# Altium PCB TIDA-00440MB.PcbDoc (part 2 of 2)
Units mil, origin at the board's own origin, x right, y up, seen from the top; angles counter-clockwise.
Board outline 4900 x 4330.71 mil, 4 copper layers (Top Layer, MidLayer1 (GND), MidLayer2 (PWR), Bottom Layer), stack 90 mil thick; 170 components, 89 nets, 419 pads, 132 vias.
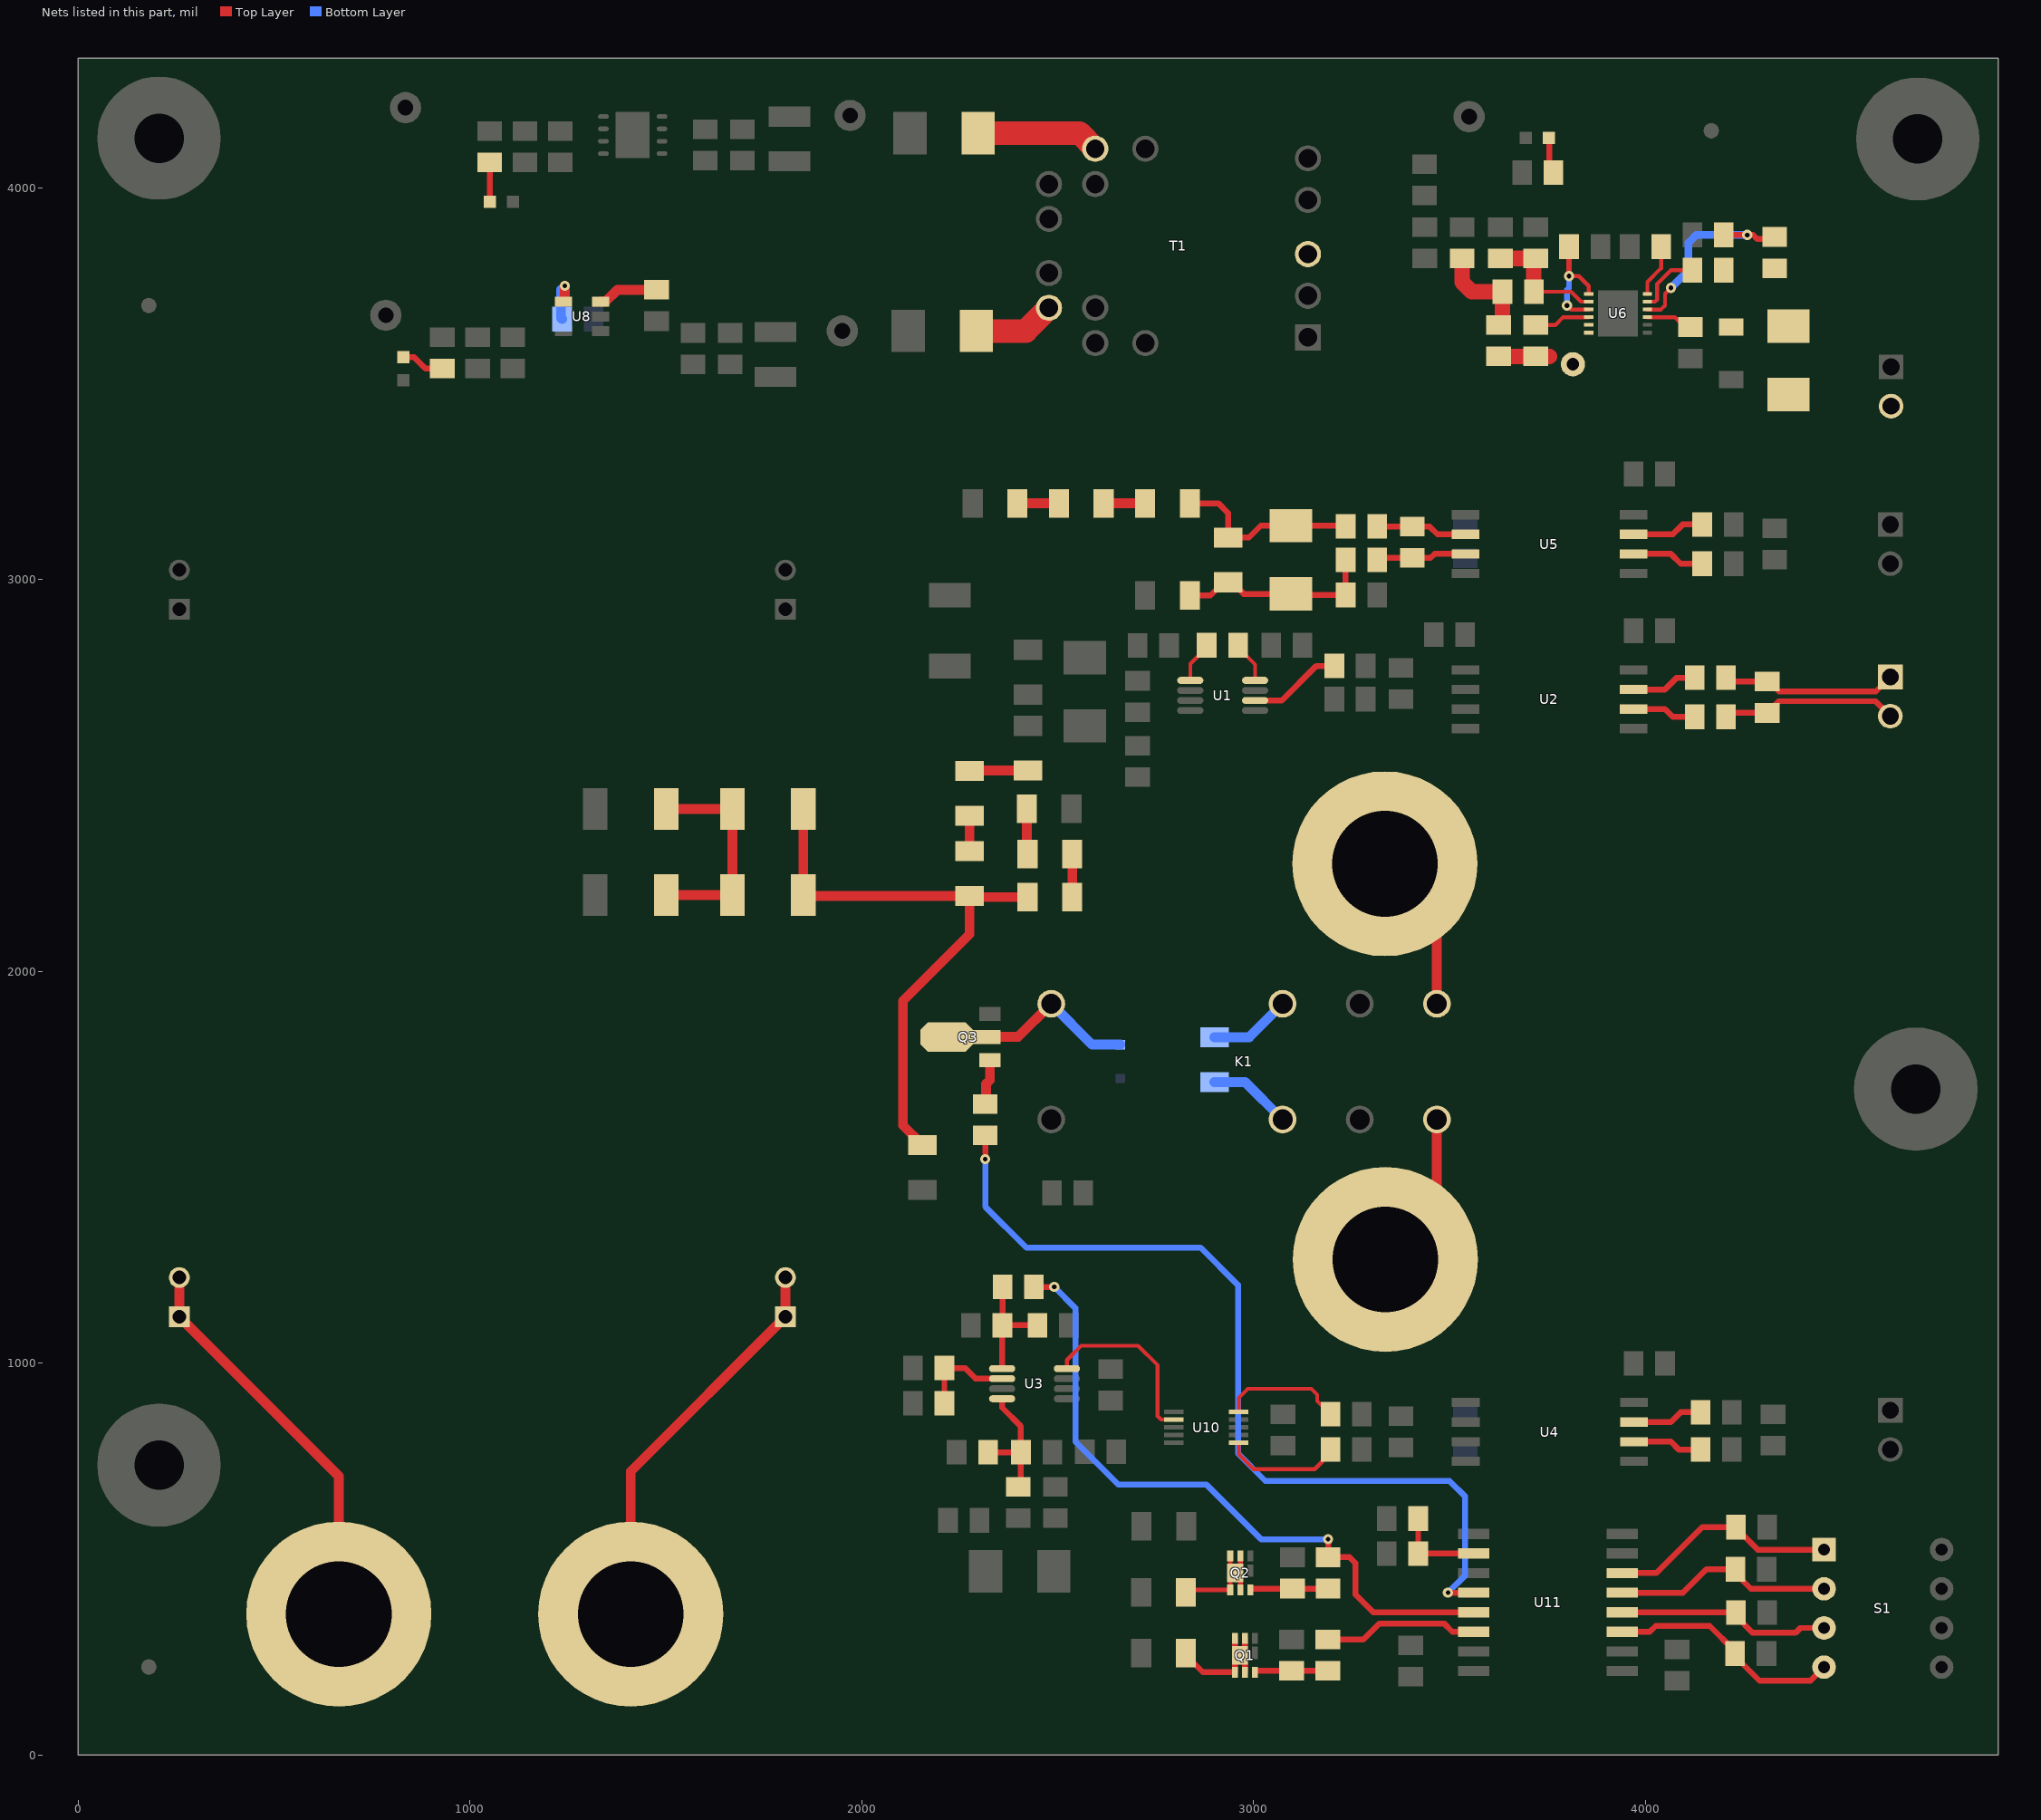
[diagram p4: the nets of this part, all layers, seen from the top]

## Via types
v1: diameter 26, hole 12, Top Layer to Bottom Layer, 122 vias
v2: diameter 19.68, hole 7.87, Top Layer to Bottom Layer, 10 vias

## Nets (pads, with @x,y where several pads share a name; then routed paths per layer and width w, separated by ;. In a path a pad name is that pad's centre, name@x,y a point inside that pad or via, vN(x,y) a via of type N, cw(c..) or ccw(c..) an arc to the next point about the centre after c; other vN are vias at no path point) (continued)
NetC6_2: C6.2 C43.1 R24.2 U3.8 | length 331.4
  Top Layer w15: C43.1@2322,773 C6.2@2406,773 ; U3.8@2358.01,909.61 2358.01,886.99 2406,839 C6.2@2406,773 ; R24.2@2399,685 2406,692 C6.2@2406,773
NetC7_1: C7.1 R22.2 U5.2 | length 233.7
  Top Layer w15: R22.2@3315,3136 C7.1@3405,3136 3449,3136 3469,3116 U5.2@3540.43,3116
NetC7_2: C7.2 R29.2 U5.3 | length 231.6
  Top Layer w15: R29.2@3315,3051 3320,3056 C7.2@3405,3056 3452,3056 3462,3066 U5.3@3540.43,3066
NetC11_1: C11.1 U6.6 | length 135.4
  Top Layer w10: U6.6@4004.8,3729.21 4004.8,3759.8 4040,3795 C11.1@4040,3850
NetC22_1: C22.1 U6.10 | length 143.5
  Top Layer w10: C22.1@3720,3650 3770,3650 3790.16,3670.16 U6.10@3855.2,3670.16
NetC22_2: C22.2 R48.1 SW.1 T1.3 U6.11 U6.12 | length 110
  Top Layer w40: R48.1@3645,3570 3755,3570
NetC24_2: C24.2 C31.2 R48.2 | length 262.5
  Top Layer w40: C24.2@3532,3820 3532,3760 3557,3735 C31.2@3635,3735 3635,3660 R48.2@3625,3650
NetC28_1: C28.1 C29.1 D4.1 R46.2 R49.1 U6.3 | length 120.6
  Top Layer w10: U6.3@4004.8,3670.16 4074.84,3670.16 4100,3645 C29.1@4115,3645
NetC30_1: C30.1 U8.4 | length 118.3
  Top Layer w25: U8.4@1238.44,3709.4 1242,3712.96 v1(1242,3750)
  Bottom Layer w25: 1232,3740 1232,3668 C30.1@1235,3665
NetC31_1: C31.1 R50.1 R52.2 U6.8 | length 305.7
  Top Layer w10: C31.1@3725,3735 3810,3735 3835.47,3709.53 U6.8@3855.2,3709.53
  Top Layer w40: R50.1@3630,3820 R52.2@3720,3820 ; C31.1@3715,3735 R52.2@3715,3810
NetC34_1: C34.1 U6.7 U6.9 | length 292.7
  Top Layer w10: v1(3800,3700) 3810.16,3689.84 U6.9@3855.2,3689.84 ; v1(3805,3775) 3830,3775 3855.2,3749.8 U6.7@3855.2,3729.21
  Top Layer w15: v1(3805,3775) C34.1@3805,3850
  Bottom Layer w15: v1(3800,3700) 3800,3740 3805,3745 v1(3805,3775)
NetD1_2: D1.2 K1.8 Q3.2 Q3.4 | length 521.7
  Top Layer w25: Q3.4@2216.57,1833 Q3.2@2318.93,1833 2398.76,1833 K1.8@2483.4,1917.64
  Bottom Layer w25: K1.8@2483.4,1917.64 2587.73,1813.31 D1.2@2660,1813.31
NetD2_2: D2.2 T1.11 | length 327.2
  Top Layer w60: D2.2@2297.01,4140 2555.63,4140 T1.11@2595.6,4100.03 ; D2.2@2299.5,4125.5 D2.2@2299.5,4137.51
NetD3_2: D3.2 T1.15 | length 210
  Top Layer w60: D3.2@2292.01,3635 2418.36,3635 T1.15@2477.49,3694.13
NetD4_2: D4.2 J5.2
NetD5_1: D5.1 R19.1 R22.1 R27.2 | length 483.9
  Top Layer w15: R19.1@2837.09,3195 2910,3195 2935,3170 R27.2@2935,3107.77 2988.27,3107.77 3018.51,3138.01 D5.1@3095,3138.01 3232.99,3138.01 R22.1@3235,3136
NetD5_2: D5.2 R27.1 R29.1 R56.2 R57.2 | length 515.3
  Top Layer w15: R57.2@2837.09,2960 2890,2960 2923.6,2993.6 R27.1@2935,2993.6 2945.24,2993.6 2974.84,2963.99 D5.2@3095,2963.99 3107.99,2963.99 3110.98,2961 R56.2@3235,2961 R29.1@3235,3051
NetD6_1: D6.1 R1.2 | length 93.3
  Top Layer w15: D6.1@3754.53,4128 3754.53,4049.47 R1.2@3765,4039
NetD7_1: D7.1 R53.2 | length 100.2
  Top Layer w15: R53.2@1050,4065 1050,3965.47 D7.1@1050.47,3965
NetD8_1: D8.1 R54.2 | length 111.5
  Top Layer w15: D8.1@829.69,3568.46 856.54,3568.46 886,3539 R54.2@929,3539
NetJ1_1: J1.1 JD1.1 JD1.2 | length 1027.7
  Top Layer w25: JD1.2@257.76,1219 JD1.1@257.76,1119 665,711.76 J1.1@665,360
NetJ2_1: J2.1 JD2.1 JD2.2 | length 1022.6
  Top Layer w25: J2.1@1410,360 1410,724 JD2.1@1805,1119 JD2.2@1805,1219
NetJ3_1: J3.1 K1.4 | length 446.9
  Top Layer w25: J3.1@3336,1230 3467.65,1361.65 K1.4@3467.65,1622.36
NetJ4_1: J4.1 K1.5 | length 412.3
  Top Layer w25: J4.1@3335,2275 3467.65,2142.35 K1.5@3467.65,1917.64
NetK1_2: K1.2 R35.2 | length 213.5
  Bottom Layer w25: R35.2@2900,1717.91 2978.4,1717.91 K1.2@3073.95,1622.36
NetK1_7: K1.7 R35.1 | length 209.4
  Bottom Layer w25: R35.1@2900,1832.09 2988.4,1832.09 K1.7@3073.95,1917.64
NetQ1_1: Q1.1 Q1.2 Q1.5 Q1.6 Q1.7 R11.1 | length 268.2
  Top Layer w15: R11.1@2832.09,260 2832.09,249.76 2870.16,211.69 Q1.1@2952.21,211.69 Q1.7@2952.21,242.21 ; Q1.7@2952.21,267.79 Q1.6@2952.21,298.31 ; Q1.2@2977.8,211.69 Q1.7@2977.8,242.2 ; Q1.7@2977.8,267.8 Q1.5@2977.8,298.31
NetQ1_3: Q1.3 R14.2 R16.2 | length 187.1
  Top Layer w15: Q1.3@3003.39,211.69 3006.7,215 R16.2@3097.11,215 R14.2@3189.11,215
NetQ2_1: Q2.1 Q2.2 Q2.5 Q2.6 Q2.7 R12.1 | length 268.1
  Top Layer w12: R12.1@2832.09,418 2835.78,421.69 Q2.1@2940.41,421.69 Q2.7@2940.41,452.21 ; Q2.6@2940.41,508.31 2940.41,477.79 Q2.7@2953.2,465 2966,477.8 Q2.5@2966,508.31 ; Q2.2@2966,421.69 Q2.7@2966,452.2
NetQ2_3: Q2.3 R15.2 R17.2 | length 199.8
  Top Layer w15: Q2.3@2991.59,421.69 2994.9,425 R17.2@3099,425 R15.2@3190,425
NetQ3_1: Q3.1 R36.1 | length 116
  Top Layer w25: R36.1@2317,1662 2317,1713 2326.8,1722.8 Q3.1@2326.8,1773.94
NetR2_2: R2.2 R59.1 R61.2 R62.1 | length 557.8
  Top Layer w25: R61.2@1500.55,2195 R62.1@1669.45,2195 R59.1@1669.45,2415 R2.2@1500.55,2415
NetR3_2: R3.2 R58.1 | length 149.3
  Top Layer w25: R58.1@2275,2512.09 2275.83,2512.91 R3.2@2424,2512.91
NetR4_1: R4.1 U1.6 | length 238.8
  Top Layer w15: U1.6@3003.68,2691.89 3071.89,2691.89 3160,2780 R4.1@3206,2780
NetR5_1: R5.1 U2.7 | length 168.9
  Top Layer w15: U2.7@3969.57,2720 4050,2720 4080,2750 R5.1@4126,2750
NetR7_1: R7.1 U2.6 | length 164.7
  Top Layer w15: U2.6@3969.57,2670 4050,2670 4070,2650 R7.1@4126,2650
NetR10_1: R10.1 U1.1 | length 124.2
  Top Layer w10: U1.1@2838.32,2743.07 2838.32,2785.32 2880.69,2827.69 R10.1@2880.69,2849.69
NetR10_2: R10.2 U1.8 | length 124.4
  Top Layer w10: R10.2@2960.69,2849.69 2960.69,2826.31 3003.68,2783.32 U1.8@3003.68,2743.07
NetR18_1: R18.1 U10.10 | length 316
  Top Layer w10: U10.10@2962,876 2962,912 2985,935 3147.25,935 3162.25,920 3162.25,903.75 R18.1@3196,870
NetR19_2: R19.2 R65.1 | length 105.8
  Top Layer w25: R65.1@2617.09,3195 R19.2@2722.91,3195
NetR21_1: R21.1 U4.7 | length 180.8
  Top Layer w15: U4.7@3970.57,850 4065,850 4090,875 R21.1@4141,875
NetR23_1: R23.1 U4.6 | length 178.7
  Top Layer w15: U4.6@3970.57,800 4065,800 4085,780 R23.1@4141,780
NetR25_1: R25.1 U10.6 | length 305.5
  Top Layer w10: U10.6@2962,797.2 2962,768 3000,730 3156,730 3196,770 R25.1@3196,780
NetR26_1: R26.1 U5.7 | length 185.8
  Top Layer w15: U5.7@3969.57,3116 4070,3116 4095,3141 R26.1@4145,3141
NetR28_1: R28.1 U5.6 | length 185.8
  Top Layer w15: U5.6@3969.57,3066 4065,3066 4090,3041 R28.1@4145,3041
NetR30_2: R30.2 R33.2 U3.6 | length 248.6
  Top Layer w15: R30.2@2210.69,898 R33.2@2210.69,988 2263,988 2290.2,960.8 U3.6@2358.01,960.8
NetR31_2: R31.2 R32.2 R34.2 U3.5 | length 299
  Top Layer w15: U3.5@2358.01,986.39 2358.01,1096.32 R34.2@2358.69,1097 ; R32.2@2359,1195 2358.69,1194.69 R34.2@2358.69,1097 ; R31.2@2448.68,1097 R34.2@2358.69,1097
NetR37_1: R37.1 S1.1 U11.6 | length 589.1
  Top Layer w15: U11.6@3940.4,464.64 4027.64,464.64 4145,582 R37.1@4231,582 4231,580.07 4286.53,524.53 S1.1@4456,524.53
NetR38_1: R38.1 S1.2 U11.5 | length 566.5
  Top Layer w15: U11.5@3940.4,414.64 4096,414.64 4155.36,474 R38.1@4230,474 4230,464 4269.47,424.53 S1.2@4456,424.53
NetR39_1: R39.1 S1.3 U11.4 | length 527
  Top Layer w15: U11.4@3940.4,364.64 R39.1@4210.37,364.64 ; R39.1@4231,364 4231,355 4274,312 4383,312 4395.53,324.53 S1.3@4456,324.53
NetR40_1: R40.1 S1.4 U11.3 | length 609.6
  Top Layer w15: U11.3@3940.4,314.64 4011,314.64 4026.36,330 4164,330 4226,268 R40.1@4226,250 ; R40.1@4229,259 4229,252 4291,190 4421.47,190 S1.4@4456,224.54
NetR41_2: R41.2 R42.2 U11.10 | length 231.7
  Top Layer w15: R42.2@3420,604 R41.2@3420,514 3420.64,514.64 U11.10@3561.4,514.64
NetR43_2: R43.2 R63.1 | length 115.8
  Top Layer w25: R43.2@2420.91,2415 2420.91,2302 R63.1@2422.91,2300
NetR44_1: R44.1 R58.2 | length 90.8
  Top Layer w25: R44.1@2275,2307.09 R58.2@2275,2397.91
NetR44_2: R44.2 R45.2 R59.2 R60.2 R62.2 | length 1521.4
  Top Layer w25: R59.2@1850.55,2415 R62.2@1850.55,2195 1852.64,2192.91 R44.2@2275,2192.91 ; R45.2@2155,1557.09 2105,1607.09 2105,1925 2275,2095 R44.2@2275,2192.91 ; R60.2@2422.91,2190 2277.91,2190 R44.2@2275,2192.91
NetR46_1: R46.1 R51.2 U6.4 | length 528.8
  Top Layer w10: U6.4@4004.8,3689.84 4039.84,3689.84 4050,3700 4050,3730 v1(4065,3745)
  Top Layer w15: R51.2@4200,3880 v1(4260,3880) 4275,3880 4285,3870 4325,3870 R46.1@4330,3875
  Bottom Layer w20: v1(4065,3745) 4110,3790 4110,3860 4130,3880 v1(4260,3880)
NetR47_1: R47.1 U8.3 | length 155.7
  Top Layer w25: U8.3@1332.93,3709.4 1345.4,3709.4 1376,3740 R47.1@1476,3740
NetR49_2: R49.2 U6.5 | length 172
  Top Layer w10: U6.5@4004.8,3709.53 4024.53,3709.53 4030,3715 4030,3755 4065,3790 R49.2@4120,3790
NetR60_1: R60.1 R63.2 | length 110
  Top Layer w25: R60.1@2537.09,2190 R63.2@2537.09,2300
NetR64_1: R64.1 R65.2 | length 105.8
  Top Layer w25: R64.1@2397.09,3195 R65.2@2502.91,3195
NetU3_4: U3.4 U10.2 | length 464.1
  Top Layer w10: U3.4@2523.36,986.39 2523.36,1008.36 2560,1045 2705,1045 2755,995 2755,865 2763.7,856.3 U10.2@2796,856.3
RDM(+): C3.1 J7.1 R5.2 | length 454.7
  Top Layer w15: R5.2@4206,2750 4206,2740 C3.1@4311,2740 4316,2740 4341,2715 4588,2715 J7.1@4625,2752
RDM(-): C3.2 J7.2 R7.2 | length 457.2
  Top Layer w15: R7.2@4206,2650 4206,2660 C3.2@4311,2660 4341,2690 4587,2690 J7.2@4625,2652
RELAY: R36.2 U11.12 | length 2299.2
  Top Layer w15: v1(2315,1521) R36.2@2315,1582 ; v1@3492,415 v1@3496,415 ; v1@3492.36,414.64 v1@3493,414 ; v1@3496.18,414.82 3496.36,414.64 U11.12@3561.4,414.64
  Bottom Layer w15: v1(2315,1521) 2315,1400 2420,1295 2865,1295 2960,1200 2960,770 3030,700 3500,700 3540,660 3540,458.64 v1(3496,414.64)
SW1: R14.1 U11.14 | length 398.1
  Top Layer w15: R14.1@3189.11,295 3280,295 3321,336 3486,336 3507.36,314.64 U11.14@3561.4,314.64
SW2: R15.1 R32.1 U11.13 | length 1739.9
  Top Layer w15: R32.1@2439,1195 v1(2491,1195) ; v1(3190,551) R15.1@3190,505 3245,505 3260,490 3260,410 3305.36,364.64 U11.13@3561.4,364.64
  Bottom Layer w15: v1(2491,1195) 2545,1141 2545,800 2655,690 2880,690 3019,551 v1(3190,551)
pads on no net: FID1.1 FID2.1 FID3.1 FID4.1 FID5.1 FID6.1 H1.1 H2.1 H3.1 H4.1 LBL1.0 T1.1 T1.2 T1.5 T1.6 T1.7 T1.9 T1.10 T1.13 T1.14 U7.8 U11.7

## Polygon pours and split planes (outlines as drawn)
NetD4_2 on Top Layer "Multi-Layer-No Net" (solid, remove dead copper, pour order 28): 4286.5,3495 4301.5,3510 4495,3510 4530,3475 4655,3475 4680,3450 4680,3310 4655,3285 4320,3285 4285,3320 4286.5,3321.5
NetC22_2 on Top Layer "Multi-Layer-No Net" (solid, remove dead copper, pour order 23): 3105,3850 3120,3865 3285,3865 3350,3800 3350,3675 3430,3595 3805,3595 3815,3605 3815,3640 3830,3655 3865,3655 3865,3520 3845,3500 3365,3500 3250,3615 3250,3745 3200,3795 3110,3795 3105,3800
GND on Top Layer "Multi-Layer-No Net" (solid, remove dead copper, pour order 36): 3100,4250 3125,4275 4465,4275 4510,4230 4510,3985 4565,3930 4795,3930 4825,3900 4825,1950 4775,1900 4545,1900 4495,1850 4495,1545 4540,1500 4775,1500 4825,1450 4825,75 4800,50 3925,50 3900,75 3900,3275 3700,3475 3225,3475 3100,3600
5V_VCC2 on Top Layer "Multi-Layer-No Net" (solid, remove dead copper, pour order 20): 1250,3635 1180,3635 1165,3650 1165,3710 1130,3750 770,3750 715,3695 715,3605 735,3585 770,3585 800,3615 865,3615 885,3595 1245,3595 1250,3600
5V_VCC1 on Top Layer "Multi-Layer-No Net" (solid, remove dead copper, pour order 27): 1355,4115 1350,4110 1275,4110 1265,4120 1015,4120 1000,4135 1000,4150 985,4165 790,4165 770,4185 770,4255 785,4270 1340,4270 1355,4255
3V3 on Top Layer "Multi-Layer-No Net" (solid, remove dead copper, pour order 21): 3120,4000 3320,4000 3330,4000 3335,4005 3460,4005 3555,4005 3630,4005 3665,3970 3665,3890 3665,3880 3660,3875 3520,3875 3320,3875 3275,3920 3260,3935 3140,3935 3120,3935 3105,3950 3105,3990 3105,3995 3110,4000 3120,4000
ISENSE on Top Layer "Multi-Layer-No Net" (solid, remove dead copper, pour order 30): 2460,630 2560,630 2615,685 2720,685 2740,665 2740,165 2700,125 2470,125 2450,145 2450,535 2460,545
MID on Top Layer "Multi-Layer-No Net" (solid, remove dead copper, pour order 31): 2430,630 2275,630 2270,625 2270,535 2250,515 2210,515 2180,485 2180,235 2215,200 2320,200 2355,235 2355,490 2430,565
MID on Top Layer "Multi-Layer-No Net" (solid, remove dead copper, pour order 29): 2805,550 2815,540 2980,540 2985,535 2985,455 3030,455 3035,460 3035,475 3040,480 3135,480 3140,485 3140,590 3060,670 2820,670 2805,655
NetC28_1 on Top Layer "Multi-Layer-No Net" (solid, remove dead copper, pour order 26): 4060,3675 4060,3630 4070,3620 4275,3620 4295,3600 4470,3600 4490,3620 4490,3800 4470,3820 4175,3820 4175,3725 4160,3710 4095,3710
Net6V_VCC1_1 on Top Layer "Multi-Layer-No Net" (solid, remove dead copper, pour order 19): 1475,4120 1480,4115 1540,4115 1550,4125 1610,4125 1730,4125 1760,4155 1860,4155 1900,4155 2040,4015 2140,4015 2145,4015 2165,4035 2165,4235 2165,4240 2125,4280 1865,4280 1495,4280 1475,4260 1475,4120
Net6V_VCC2_1 on Top Layer "Multi-Layer-No Net" (solid, remove dead copper, pour order 22): 1425,3640 1445,3660 1445,3685 1525,3685 1550,3710 1550,3750 1580,3780 2120,3780 2160,3740 2160,3510 2125,3475 2010,3475 1880,3605 1505,3605 1475,3575 1475,3500 1450,3475 1330,3475 1310,3495 1310,3630 1320,3640
GND1 on MidLayer1 (GND) "Multi-Layer-No Net" (solid, remove dead copper, pour order 25): 2750,4255 2730,4275 425,4275 400,4250 400,3975 370,3945 85,3945 50,3910 50,975 100,925 380,925 425,880 425,775 475,725 1650,725 1750,625 1750,100 1800,50 3575,50 3600,75 3600,1615 3560,1655 2780,1655 2700,1735 2700,1970 2670,2000 685,2000 450,2235 450,3730 670,3950 1175,3950 1225,4000 2425,4000 2450,3975 2705,3975 2750,4020
GND on MidLayer1 (GND) "Multi-Layer-No Net" (solid, remove dead copper, pour order 35): 3100,4250 3125,4275 4475,4275 4500,4250 4500,3950 4525,3925 4800,3925 4825,3900 4825,1925 4800,1900 4590,1900 4500,1810 4500,1600 4600,1500 4805,1500 4825,1480 4825,75 4800,50 3925,50 3900,75 3900,3275 3700,3475 3225,3475 3100,3600
GND2 on MidLayer1 (GND) "Multi-Layer-No Net" (solid, remove dead copper, pour order 33): 2750,3725 2700,3775 795,3775 715,3695 715,3555 800,3470.33 800,2400 875,2325 3000,2325 3050,2275 3050,2125 3175,2000 3175,1900 3200,1875 3550,1875 3575,1900 3575,3175 3550,3200 2975,3200 2750,3425
5V_VCC1 on MidLayer2 (PWR) "Multi-Layer-No Net" (solid, remove dead copper, pour order 24): 2750,4255 2730,4275 425,4275 400,4250 400,3975 370,3945 85,3945 50,3910 50,975 100,925 380,925 425,880 425,775 475,725 1650,725 1750,625 1750,100 1800,50 3575,50 3600,75 3600,1615 3560,1655 2780,1655 2700,1735 2700,1970 2670,2000 685,2000 450,2235 450,3730 670,3950 1175,3950 1225,4000 2425,4000 2450,3975 2705,3975 2750,4020
3V3 on MidLayer2 (PWR) "Multi-Layer-No Net" (solid, remove dead copper, pour order 34): 3100,4250 3125,4275 4475,4275 4500,4250 4500,3950 4525,3925 4800,3925 4825,3900 4825,1925 4800,1900 4590,1900 4500,1810 4500,1600 4600,1500 4805,1500 4825,1480 4825,75 4800,50 3925,50 3900,75 3900,3275 3700,3475 3225,3475 3100,3600
5V_VCC2 on MidLayer2 (PWR) "Multi-Layer-No Net" (solid, remove dead copper, pour order 32): 2750,3725 2700,3775 795,3775 715,3695 715,3555 800,3470.33 800,2400 875,2325 3000,2325 3050,2275 3050,2125 3175,2000 3175,1900 3200,1875 3550,1875 3575,1900 3575,3175 3550,3200 2975,3200 2750,3425

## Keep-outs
Top Layer:
  lines w10: 2780,4330.71 2781,4329.71 2781,3513 3049,3245 3555,3245 3615,3185 3615,1425 3615,933.52 3615,-20 3880,-20 3885,-20 3885,45 3885,980 3885,3255 3690,3450 3214,3450 3086,3578 3086,4330.71 2801,4330.71 2780,4330.71
MidLayer1 (GND):
  lines w10: 2781,4329.71 2781,3513 3049,3245 3555,3245 3615,3185 3615,-20 3885,-20 3885,3255 3690,3450 3214,3450 3086,3578 3086,4330.71
MidLayer2 (PWR):
  lines w10: 2781,3513 3049,3245 3555,3245 3615,3185 3615,-20 3885,-20 3885,3255 3690,3450 3214,3450 3086,3578 3086,4330.71 3085,4329.71 2781,4329.71 2781,3513
Bottom Layer:
  lines w10: 3086,4330.71 3085,4329.71 ; 3085,4329.71 2781,4329.71 2781,3513 3049,3245 3555,3245 3615,3185 3615,-20 3885,-20 3885,3255 3690,3450 3214,3450 3085,3579 3085,4329.71
Keep-Out Layer:
  lines w8: 25,25 4875,25 4875,4305 25,4305 25,25
  text ".Layer_Name" at 132,-1113.49 h60

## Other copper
Top Layer:
  pour cut-out: 4077,3852 4162,3852 4163,3851 4163,3832.96 4077.54,3832.96 4077,3833.5
  text ".Layer_Name" at 132,-1113.49 h60
MidLayer1 (GND):
  text ".Layer_Name" at 120,-1110 h60
MidLayer2 (PWR):
  text ".Layer_Name" at 120,-1110 h60
Bottom Layer:
  text ".Layer_Name" at 132,-1113.49 h60

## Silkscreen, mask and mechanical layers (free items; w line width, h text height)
Top Overlay:
  circle w6: c2484.69,1498 r11.31
  lines w6: 1945,3715 1945,3775 ; 1970,4070 1970,4110 ; 2385.31,830 2391,830 2398,823 ; 2630,2900 2636,2894 2646,2894 2660,2880 ; 2655,547 2573,547 ; 2796,2621 2796,2626 2777,2645 2756,2645 ; 3554,3981 3578,3957 3595,3957 3610,3942 ; 3608,3981 3619,3970 3661,3970 3686,3945 ; 4800,425 4815,425 ; 2573,547 2574,547 2581,540 2581,555 2573,547 ; 2756,2645 2762,2639 2763,2639 2763,2652 2756,2645 ; 3610,3942 3610,3952 3600,3942 3610,3942 ; 3686,3945 3686,3955 3676,3945 3686,3945 ; 2835,785 2835,875 2840,880 2850,890 2925,890 2925,785 2835,785 ; 3650,175 3825,175 3850,200 3850,600 3650,600 3650,175 ; 4525,175 4525,550 4550,575 4695,575 4695,175 4525,175
  lines w10: 3207,3309 3207,3210 ; 3207,3210 3197,3220 3218,3220 3208,3210 3207,3210
  text "GND" at 4550,3660 h60
  text "VIN+" at 4530,3255 h60
  text "MATCH JD1 TO JD4 WHILE" at 610,1635 h60 r90
  text "MOUNTING DAUGHTER BOARD" at 750,1635 h60 r90
  text "JD1 AND JD2 - INPUT" at 925,1630 h60 r90
  text "JD3 AND JD4 - OUTPUT" at 1060,1625 h60 r90
  text "MUX" at 4800,530 h30
  text "RELAY" at 4855,355 h30 r90
  text "SW2" at 4800,305 h30
  text "SW1" at 4805,205 h30
  text "HV_DC(-)" at 1780,140 h50 r90
  text "HV_DC(+)" at 359,130 h50 r90
  text "TIDA-00440MB-E2" at 1945,120 h80
  text ".Layer_Name" at 132,-1113.49 h60
Bottom Overlay:
  text ".Layer_Name" at 132,-1113.49 h60
Top Paste:
  text ".Layer_Name" at 132,-1113.49 h60
Bottom Paste:
  text ".Layer_Name" at 132,-1113.49 h60
Top Solder:
  text ".Layer_Name" at 132,-1113.49 h60
Bottom Solder:
  text ".Layer_Name" at 132,-1113.49 h60
Drill Guide:
  text ".Layer_Name" at 132,-1113.49 h60
M1 Board Outline:
  the board outline again, w10
M2 Board Dimensions:
  rectangle: -445.5,-540.5 -320.5,-415.5
  rectangle: -320.5,-665.5 54.5,-540.5
  lines w7: -445.5,-540.5 554.5,-540.5 ; -320.5,-665.5 -320.5,-415.5 ; -195.5,-665.5 -195.5,-415.5 ; 54.5,-665.5 54.5,-415.5 ; 304.5,-665.5 304.5,-415.5 ; -445.5,-665.5 554.5,-665.5 554.5,-415.5 -445.5,-415.5 -445.5,-665.5
  lines w10: -445.5,-730.5 -445.5,-710.5 ; -385.5,-740.5 -445.5,-720.5 ; -385.5,-700.5 -445.5,-720.5 ; -221.42,-720.5 -445.5,-720.5 ; 330.42,-720.5 554.5,-720.5 ; 494.5,-740.5 554.5,-720.5 ; 494.5,-700.5 554.5,-720.5 ; 554.5,-730.5 554.5,-710.5
  text "1000 (mil)" at -211.42,-756.49 h60
M3 3D STEP Top:
  text ".Layer_Name" at 132,-1113.49 h60
M4 3D STEP Bottom:
  text ".Layer_Name" at 132,-1113.49 h60
M5 Assembly Top:
  circle w6: c1333,3600 r4.85
  circle w10: c3138.79,3620 r21.21
  circle w10: c2484.5,1620 r25.5
  lines w6: 1275.84,3610.98 1288.98,3610.98 1295.53,3617.53 1295.53,3733.02 1275.84,3733.02 1275.84,3610.98
  lines w10: -737,-1185.17 5863,-1185.17 ; -737,-981.83 5865,-981.83 ; -737,-778.5 -737,-1388.5 3268,-1388.5 5865,-1388.5 5865,-778.5 -736.5,-778.5 -736.5,-1388.5 839,-1388.5 ; 1728,-1388.5 1728,-778.5 ; 2995,-981.83 2995,-778.5 ; 3835,-981.83 3835,-778.5 ; 4457,-1395 4457,-1192.17 ; 7.76,694 7.76,3449.91 2055,3449.91 2055,694 7.76,694
  text "COMPONENTS MARKED 'DNP' SHOULD NOT BE POPULATED." at 708.5,-573.5 h35
  text "ASSEMBLY VARIANT:" at 708,-689 h35
  text ".VariantName" at 1744,-689 h35
  text "TIDA-00440MB" at 2190,-910 h60
  text "PCB VIEWED FROM TOP SIDE" at -673.5,-910.67 h35
  text "BOARD #:" at 1803,-910.67 h35
  text "REV:" at 3193,-910.67 h35
  text ".PCB_Rev" at 3484.5,-910.67 h60
  text "SVN REV:" at 4031,-910.67 h35
  text ".VersionControl_RevNumber" at 4537,-910.67 h35
  text "IGNORE ->" at -673.5,-1113.49 h35
  text "ASSEMBLY TOP" at 295,-1115 h60
  text "PLOT NAME =" at -673.5,-1319.34 h35
  text ".plot_File_Name" at 132,-1319.34 h35
  text "GENERATED    :" at 1805,-1319.34 h35
  text ".Print_Date" at 2674.5,-1319.34 h35
  text ".Print_Time" at 3403.5,-1319.34 h35
  text "TEXAS INSTRUMENTS" at 4668,-1319.34 h35
M6 Assembly Bottom:
  lines w10: -737.5,-982.33 5864.5,-982.33 ; -735.5,-1185.67 5864.5,-1185.67 ; 670.5,-1395.5 670.5,-1192.67 ; 1292.5,-982.33 1292.5,-779 ; 2132.5,-982.33 2132.5,-779 ; 3399.5,-1389 3399.5,-779 ; 4288.5,-1389 5864,-1389 5864,-779 -737.5,-779 -737.5,-1389 1859.5,-1389 5864.5,-1389 5864.5,-779
  text "COMPONENTS MARKED 'DNP' SHOULD NOT BE POPULATED." at 5657,-573 h60
  text ".VariantName" at 4613,-689 h60
  text "ASSEMBLY VARIANT:" at 5652,-689 h60
  text ".VersionControl_RevNumber" at 590.5,-911.17 h60
  text "SVN REV:" at 1096.5,-911.17 h60
  text ".PCB_Rev" at 1643,-911.17 h60
  text "REV:" at 1934.5,-911.17 h60
  text "BOARD #:" at 3324.5,-911.17 h60
  text "PCB VIEWED FROM BOTTOM SIDE" at 5801,-911.17 h60
  text "TIDA-00440MB" at 2870,-915 h60
  text "IGNORE ->" at 2102.85,-1113.49 h60
  text "ASSEMBLY BOTTOM" at 1175,-1130 h60
  text "TEXAS INSTRUMENTS" at 459.5,-1319.84 h60
  text ".Print_Time" at 1724,-1319.84 h60
  text ".Print_Date" at 2453,-1319.84 h60
  text "GENERATED    :" at 3322.5,-1319.84 h60
  text ".plot_File_Name" at 4995.5,-1319.84 h60
  text "PLOT NAME =" at 5801,-1319.84 h60
M9 Title Sheet:
  drawing of 57 lines, arcs and shapes, not listed
  text "1" at 294.84,7781.5 h70
  text "2" at 2790.5,7781.5 h70
  text "3" at 5279.84,7781.5 h70
  text "4" at 7786.51,7781.5 h70
  text "5" at 10285.5,7781.5 h70
  text "6" at 12790.5,7781.5 h70
  text "A" at -861.5,6638.5 h70
  text "A" at 13938.5,6638.5 h70
  text "B" at -861.5,4258.5 h70
  text "B" at 13938.5,4258.5 h70
  text "C" at -861.5,1883.5 h70
  text "C" at 13938.5,1883.5 h70
  text "PROJECT TITLE:" at 10898.5,22.5 h45
  text ".PRJ_Title" at 10948.5,-110.83 h70
  text "DESIGNED FOR:" at 10898.5,-278.5 h45
  text ".PRJ_Customer" at 10948.5,-418.5 h70
  text "D" at -861.5,-486.5 h70
  text "D" at 13938.5,-486.5 h70
  text "FILE NAME:" at 10898.5,-578.5 h45
  text ".PCB_File_Name_No_Path" at 10948.5,-698.5 h70
  text "Texas Instruments (TI) and/or its licensors do not warrant the accuracy or completeness of this specification" at 5929,-860.34 h45
  text "ENGINEER:" at 10898.5,-868.5 h45
  text "LAYOUT BY:" at 12403.5,-868.5 h45
  text "or any information contained therein. TI and/or its licensors do not warrant that this design will meet" at 5884.01,-973 h45
  text ".PRJ_Engineer" at 10948.5,-1023.49 h70
  text "Manjunath M" at 12454,-1023.49 h70
  text "the specifications, will be suitable for your application or fit for any particular purpose, or will operate in" at 5884.01,-1085.67 h45
  text "ALTIUM DESIGNER VERSION:" at 12403.5,-1178.5 h45
  text "an implementation. TI and/or its licensors do not warrant that the design is production worthy. You should" at 5884.01,-1198.33 h45
  text "completely validate and test your design implementation to confirm the system functionality for your application." at 5929,-1311 h45
  text ".print_Scale" at 10948.5,-1311.83 h70
  text ".Application_BuildNumber" at 12454,-1311.83 h70
  text "1" at 294.84,-1518.5 h70
  text "2" at 2790.5,-1518.5 h70
  text "3" at 5279.84,-1518.5 h70
  text "4" at 7786.51,-1518.5 h70
  text "5" at 10285.5,-1518.5 h70
  text "6" at 12790.5,-1518.5 h70
M10 Fab Notes:
  drawing of 228 lines, arcs and shapes, not listed
  text "DESIGN INFORMATION" at 11936.02,6555 h60
  text "(REFER ALSO ARRAY/PANEL PROFILING INFORMATION)" at 11574.46,6393.29 h60
  text "BOARD SIZE" at 10888.46,6389 h60
  text "124.46mm" at 11350.78,6261.18 h60
  text "X" at 11856.46,6261.18 h60
  text "110mm" at 12087.78,6261.18 h60
  text "Number of Layers :" at 11291.46,6064 h60
  text "4" at 12386.27,6054 h60
  text "MIN. TRACK WIDTH:" at 11291.46,5925 h60
  text "10" at 12387.7,5925 h60
  text "MIL" at 12542.46,5925 h60
  text "MIN. CLEARANCE:" at 11291.46,5793 h60
  text "MIL" at 12542.46,5793 h60
  text "7.87" at 12290,5785 h60
  text "MIN. VIA PAD SIZE:" at 11291.46,5661 h60
  text "MIL" at 12542.46,5661 h60
  text "19.685" at 12165,5660 h60
  text "EXTERNAL" at 12955,5520 h60
  text "0.1501mm (5.91MIL)" at 11986.46,5519.29 h60
  text "MINIMUM ANNULAR RING" at 10962.23,5515 h60
  text "PER" at 11162.23,5397 h60
  text "IPC-D-275 CLASS 2 LEVEL C" at 11382.23,5397 h60
  text "MIL, HOLES" at 12870.46,5284.71 h60
  text "+/-" at 12478,5284 h60
  text "+/-" at 13332,5284 h60
  text "REGISTRATION TOLERANCES:" at 10962.23,5279 h60
  text "METAL" at 12162,5279 h60
  text "5" at 12738.2,5279 h60
  text "3" at 13571.2,5279 h60
  text "MIL" at 13687.46,5279 h60
  text "MATERIAL:" at 10887.46,5069.54 h60
  text "FR-4 High Tg" at 11873.9,4929.21 h60
  text "X" at 11155,4924 h60
  text "FR-408" at 11308.46,4920.64 h60
  text "OTHER" at 12796.46,4920.64 h60
  text "63 MIL (1.6mm) +/-10%" at 11628.56,4757.92 h60
  text "THICKNESS:" at 10962.23,4753.64 h60
  text "X" at 11500.4,4753.64 h60
  text "OTHER" at 12913.46,4753.64 h60
  text "TOLERANCE:" at 10962.23,4595.64 h60
  text "X" at 11801.53,4595.64 h60
  text "ANSI IPC-6012 TYPE 3 CLASS 2" at 11988.48,4595.64 h60
  text "OTHER +/-" at 11988.46,4439.64 h60
  text "BOW & TWIST:" at 10962.23,4282.64 h60
  text "X" at 11801.53,4282.64 h60
  text "ANSI IPC-6012 TYPE 3 CLASS 2" at 11988.48,4282.64 h60
  text "OTHER +/-" at 11988.46,4124.13 h60
  text "COPPER THICKNESS (FINISHED):" at 10887.46,3988.64 h60
  text "1.4MIL (1oz)" at 11767.46,3835.92 h60
  text "2MIL (1.4oz)" at 12534.46,3835.92 h60
  text "2.8MIL (2oz)" at 13261.46,3835.92 h60
  text "OUTER:" at 11244.46,3831.64 h60
  text "X" at 11639,3831 h60
  text "1.4MIL (1oz)" at 11767.46,3678.92 h60
  text "2.8MIL (2oz)" at 12534.46,3678.92 h60
  text "N/A" at 13261,3679.29 h60
  text "INNER SIGNAL:" at 10955.38,3674.64 h60
  text "X" at 11639,3674 h60
  text "DRILLING:" at 10887.46,3535.64 h60
  text "REFERENCE:" at 10962.23,3418.64 h60
  text "X" at 11610.46,3418.64 h60
  text "AS SHOWN" at 11797.46,3418.64 h60
  text "X" at 12511.46,3418.64 h60
  text "NC_DRILL FILES" at 12648.46,3418.64 h60
  text "PTH MIN COPPER THICKNESS:" at 10962.23,3260.64 h60
  text "X" at 12312.46,3260.64 h60
  text "1MIL" at 12449.46,3260.64 h60
  text "OTHER" at 12946.46,3260.64 h60
  text "BOARD FINISH:" at 10887.46,3101.64 h60
  text "X" at 12496.46,2988.64 h60
  text "SILKSCREEN:" at 11042.68,2983.64 h60
  text "X" at 11991.46,2983.64 h60
  text "TOP" at 12117.46,2983.64 h60
  text "BOTTOM" at 12628.46,2983.64 h60
  text "SILKSCREEN COLOR:" at 11042.68,2816.64 h60
  text "X" at 11990.42,2816.64 h60
  text "WHITE" at 12117.46,2816.64 h60
  text "OTHER" at 12628.46,2816.64 h60
  text "SOLDER RESIST COLOR:" at 11042.68,2646.64 h60
  text "X" at 11610.42,2487.44 h60
  text "GREEN" at 11737.46,2487.44 h60
  text "BLUE" at 12328.46,2487.44 h60
  text "OTHER" at 12866.46,2487.44 h60
  text "IMMERSION GOLD (ENIG)" at 11948.46,2298.92 h60
  text "ENEPIG" at 13286,2295.64 h60
  text "SURFACE FINISH:" at 10887.46,2294.64 h60
  text "X" at 11761.51,2294.64 h60
  text "IMM. TIN/SILVER OR EQUIV" at 11217,2137.64 h60
  text "OTHER" at 12648.46,2137.64 h60
  text "ARRAY/PANEL:" at 10887.46,1958.64 h60
  text "CUT AND TRIM PER MECH LAYER 1" at 11948.46,1954.35 h60
  text "N.C. ROUTE" at 11948.46,1802.64 h60
  text "X" at 12627.46,1802.64 h60
  text "V. SCORE" at 12814.46,1802.64 h60
  text "CERTIFICATION:" at 10887.46,1665.64 h60
  text "MATERIALS AND WORKMANSHIP FOR ALL PCBS" at 11612.46,1665.64 h60
  text "TO MEET OR EXCEED THE REQUIREMENTS OF:" at 11612.46,1567.64 h60
  text "X" at 11238.96,1431.13 h60
  text "ANSI IPC-A-600F CLASS ->" at 11377.96,1431.13 h60
  text "X" at 13017.02,1431.13 h60
  text "2" at 13135.96,1431.14 h60
  text "1" at 12820.96,1429.64 h60
  text "3" at 13489.96,1429.64 h60
  text "X" at 11241.02,1271.64 h60
  text "UL 94V-0" at 11377.96,1271.64 h60
  text "X" at 12053.02,1271.64 h60
  text "RoHS" at 12189.96,1271.64 h60
  text "OTHER" at 12834.36,1271.64 h60
  text "PER ORDER" at 13231.42,1271.64 h60
  text "X" at 13205,1135 h60
  text "VIA TENTING:" at 12068,1134 h60
  text "ADDITIONAL REQUIREMENTS:" at 10887.46,1130.64 h60
  text "YES" at 12639.67,1124.92 h60
  text "NO" at 13034.47,1124.69 h60
  text "MICROSECTION:" at 10962.23,1015.64 h60
  text "YES" at 11867.96,1015.64 h60
  text "IMPEDANCE CONTROL:" at 12121,990 h60
  text "YES" at 13089,989 h60
  text "X" at 13647,982 h60
  text "NO" at 13480.47,971.69 h60
  text "REQUIRED" at 12719.46,843.49 h60
  text "BARE BOARD ELEC. TEST:" at 10952.23,840.64 h60
  text "NONE" at 12257.96,840.64 h60
  text "X" at 12592.46,840.64 h60
  text "PER ORDER" at 13311.46,840.64 h60
  text "MANUFACTURER'S UL:" at 10952.23,683.64 h60
  text "RAIL" at 12117.96,679.35 h60
  text "METAL" at 12609.77,679.35 h60
  text "X" at 12985,679 h60
  text "SILK" at 13121.46,679.35 h60
M11 Gerber Information:
  lines w10: -737,-1185.17 5863,-1185.17 ; -737,-981.83 5865,-981.83 ; -737,-778.5 -737,-1388.5 3268,-1388.5 5865,-1388.5 5865,-778.5 -736.5,-778.5 -736.5,-1388.5 839,-1388.5 ; 1728,-1388.5 1728,-778.5 ; 2995,-981.83 2995,-778.5 ; 3835,-981.83 3835,-778.5 ; 4457,-1395 4457,-1192.17
  text "TIDA-00440MB" at 2255,-910 h60
  text "ALL ARTWORK VIEWED FROM TOP SIDE" at -673.5,-910.67 h60
  text "BOARD #:" at 1803,-910.67 h60
  text "REV:" at 3193,-910.67 h60
  text ".PCB_Rev" at 3484.5,-910.67 h60
  text "SVN REV:" at 4031,-910.67 h60
  text ".VersionControl_RevNumber" at 4537,-910.67 h60
  text "LAYER NAME =" at -673.5,-1113.49 h60
  text "PLOT NAME =" at -673.5,-1319.34 h60
  text ".plot_File_Name" at 132,-1319.34 h60
  text "GENERATED    :" at 1805,-1319.34 h60
  text ".Print_Date" at 2674.5,-1319.34 h60
  text ".Print_Time" at 3403.5,-1319.34 h60
  text "TEXAS INSTRUMENTS" at 4668,-1319.34 h60
M12 Stackup:
  lines w6: 10893,7429.5 13764,7429.5 ; 10893,7542.1 13764,7542.1 ; 10833,6717 ccw(c10869,6717) 10869,6681 13788,6681 ccw(c13788,6717) 13824,6717 13824,7639 ccw(c13788,7639) 13788,7675 10869,7675 ccw(c10869,7639) 10833,7639 10833,6717
  text "Layer Stack Up Detail for: TIDA-00440MB.PcbDoc" at 10893,7570.75 h51
  text "Layer" at 10893,7500.1 h26
  text "Gerber" at 11897.8,7500.1 h26
  text "Copper" at 12556.85,7500.1 h26
  text "Dielectric" at 13258.35,7500.1 h26
  text "Name" at 10893,7448.1 h26
  text "Document" at 11897.8,7448.1 h26
  text "Thickness" at 12556.85,7448.1 h26
  text "Material" at 13258.35,7448.1 h26
  text "Top Solder Mask" at 10893,7374.73 h36
  text "(.GTS)" at 11897.8,7374.73 h36
  text "Solder Resist" at 13258.35,7374.73 h36
  text "Top Layer" at 10893,7271.19 h36
  text "(.GTL)" at 11897.8,7271.19 h36
  text "1.4mil" at 12556.85,7271.19 h36
  text "FR-408" at 13258.35,7219.42 h36
  text "MidLayer1 (GND)" at 10893,7167.65 h36
  text "(.G1)" at 11897.8,7167.65 h36
  text "1.4mil" at 12556.85,7167.65 h36
  text "FR-408" at 13258.35,7115.88 h36
  text "MidLayer2 (PWR)" at 10893,7064.1 h36
  text "(.G2)" at 11897.8,7064.1 h36
  text "1.4mil" at 12556.85,7064.1 h36
  text "FR-408" at 13258.35,7012.33 h36
  text "Bottom Layer" at 10893,6960.56 h36
  text "(.GBL)" at 11897.8,6960.56 h36
  text "1.4mil" at 12556.85,6960.56 h36
  text "Bottom Solder Mask" at 10893,6857.02 h36
  text "(.GBS)" at 11897.8,6857.02 h36
  text "Solder Resist" at 13258.35,6857.02 h36
M13 Component Bodies Top:
  text ".Layer_Name" at 132,-1113.49 h60
M14 Component Bodies Bottom:
  text ".Layer_Name" at 132,-1113.49 h60
M15 Courtyards Top:
  text ".Layer_Name" at 132,-1113.49 h60
M16 Courtyards Bottom:
  text ".Layer_Name" at 132,-1113.49 h60
Drill Drawing:
  text ".legend" at 6260,1026 h60
  text "Drill Table" at 6270,856 h60
  text "DRILL TOLERANCE" at 6264.72,742.52 h60
  text "FOR PTH +/- 3MIL" at 6265.14,633.09 h60
  text "7.874mil drill:+0/-7.874mil" at 6259,519 h60
  text "12mil drill:+0/-12mil" at 6256,406 h60
  text ".Layer_Name" at 132,-1113.49 h60

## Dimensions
4900,0 to 0,0 on M2 Board Dimensions
0,0 to 0,4330.71 on M2 Board Dimensions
